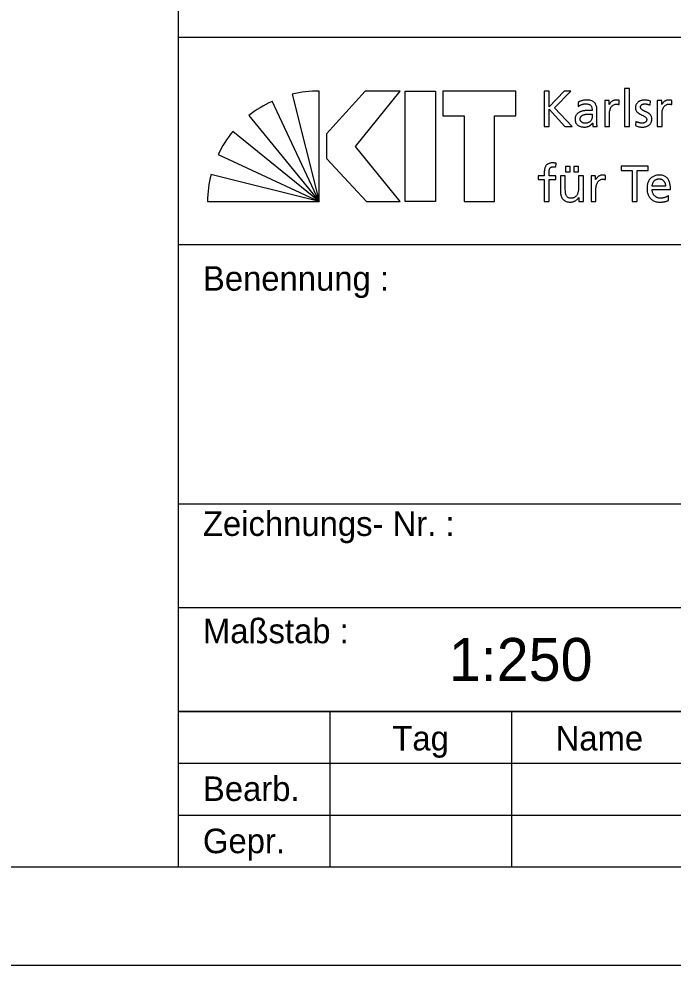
# Model space of a CAD drawing. Extents: x 0 to 105, y 0 to 74.
# Drawn here: x 78.75 to 92.08, y 0 to 19.29 of the extents above; entities that cross this region are included whole.
import ezdxf

# ---------------------------------------------------------------- set-up
doc = ezdxf.new("R2010")
doc.units = 0
doc.layers.add('90_Plankopf', color=7, linetype='Continuous')

msp = doc.modelspace()

# ---------------------------------------------------------------- linework, layer by layer
at = {"layer": '90_Plankopf'}
for p, q in [((82, 18.92), (82, 22.093)), ((82, 18.92), (103, 18.92)), ((84.319, 17.756), (84.87, 15.569)), ((84.87, 15.569), (84.87, 17.819)), ((89.452, 17.819), (89.452, 17.099)), ((84.87, 15.569), (83.908, 17.611)), ((90.145, 17.588), (90.15, 17.505)), ((90.982, 17.544), (90.982, 17.63)), ((91.614, 17.532), (91.622, 17.617)), ((92.053, 17.544), (92.053, 17.63)), ((90.53, 17.202), (90.53, 17.42)), ((83.436, 17.319), (84.87, 15.569)), ((90.433, 17.35), (90.433, 17.303)), ((91.324, 17.202), (91.319, 17.115)), ((84.87, 15.569), (83.108, 16.994)), ((89.452, 17.099), (89.556, 17.099)), ((89.876, 17.099), (90.027, 17.099)), ((82.81, 16.526), (84.87, 15.569)), ((89.693, 16.271), (89.697, 16.349)), ((84.87, 15.569), (82.664, 16.119)), ((90.707, 16.014), (90.707, 16.1)), ((91.927, 15.883), (91.654, 15.883)), ((91.654, 15.811), (92.03, 15.811)), ((91.989, 15.591), (91.989, 15.688)), ((82.591, 15.569), (84.87, 15.569)), ((82, 14.69), (103, 14.69)), ((82, 9.402), (103, 9.402)), ((82, 7.288), (103, 7.288)), ((82, 5.173), (103, 5.173)), ((82, 5.173), (103, 5.173)), ((82, 5.173), (103, 5.173)), ((82, 5.173), (103, 5.173)), ((82, 2), (82, 5.173)), ((85.088, 5.173), (85.088, 2)), ((88.794, 2), (88.794, 5.173)), ((82, 4.115), (92.5, 4.115)), ((82, 3.058), (92.5, 3.058)), ((82, 2), (103, 2)), ((82, 2), (103, 2))]:
    msp.add_line(p, q, dxfattribs=at)
for points in [[(0, 0), (105, 0), (105, 74.25), (0, 74.25)], [(2, 2), (103, 2), (103, 72.25), (2, 72.25)], [(86.517, 17.819), (85.809, 17.819), (85.018, 16.947), (85.018, 16.445), (85.834, 15.569), (86.521, 15.569), (85.606, 16.688)], [(87.243, 17.819), (87.243, 15.569), (86.625, 15.569), (86.625, 17.819)], [(87.391, 17.819), (87.391, 17.313), (87.825, 17.313), (87.825, 15.569), (88.443, 15.569), (88.443, 17.313), (88.877, 17.313), (88.877, 17.819)]]:
    msp.add_lwpolyline(points, close=True, dxfattribs=at)
for points in [[(82, 5.173), (82, 18.92)], [(90.027, 17.099), (89.662, 17.479), (90, 17.819), (89.863, 17.819), (89.556, 17.502), (89.556, 17.819), (89.452, 17.819)], [(91.095, 17.099), (91.192, 17.099), (91.192, 17.873), (91.095, 17.873), (91.095, 17.099)], [(90.78, 17.544), (90.778, 17.544), (90.778, 17.625), (90.688, 17.625), (90.688, 17.099), (90.785, 17.099), (90.785, 17.338)], [(91.852, 17.544), (91.85, 17.544), (91.85, 17.625), (91.759, 17.625), (91.759, 17.099), (91.856, 17.099), (91.856, 17.338)], [(89.556, 17.099), (89.556, 17.452), (89.876, 17.099)], [(90.441, 17.167), (90.443, 17.167), (90.443, 17.099), (90.534, 17.099)], [(89.889, 16.279), (89.889, 16.176), (89.986, 16.176), (89.986, 16.279), (89.889, 16.279)], [(90.058, 16.279), (90.058, 16.176), (90.155, 16.176), (90.155, 16.279), (90.058, 16.279)], [(91.248, 15.569), (91.351, 15.569), (91.351, 16.198), (91.575, 16.198), (91.575, 16.289), (91.024, 16.289), (91.024, 16.198), (91.248, 16.198), (91.248, 15.569)], [(89.456, 16.144), (89.456, 16.095), (89.332, 16.095), (89.332, 16.017), (89.456, 16.017), (89.456, 15.569), (89.553, 15.569), (89.553, 16.017), (89.692, 16.017), (89.692, 16.095), (89.553, 16.095), (89.553, 16.152)], [(89.885, 15.823), (89.885, 16.095), (89.788, 16.095), (89.788, 15.783)], [(90.254, 15.569), (90.254, 16.095), (90.157, 16.095), (90.157, 15.852)], [(90.506, 16.014), (90.504, 16.014), (90.504, 16.095), (90.413, 16.095), (90.413, 15.569), (90.51, 15.569), (90.51, 15.808)], [(90.158, 15.653), (90.16, 15.653), (90.16, 15.569), (90.254, 15.569)], [(103, 5.173), (82, 5.173)], [(82, 5.173), (82, 5.173)], [(82, 2), (103, 2)]]:
    msp.add_lwpolyline(points, dxfattribs=at)
for centre, start, end in [((84.862, 15.437), 89.8053, 103.1895), ((84.915, 15.452), 115.0126, 128.3968), ((84.954, 15.488), 140.7898, 154.174), ((84.973, 15.532), 165.7222, 179.1064)]:
    msp.add_arc(centre, 2.382, start, end, dxfattribs=at)
for points in [[(90.53, 17.42), (90.53, 17.468), (90.523, 17.508), (90.508, 17.54), (90.494, 17.572), (90.471, 17.597), (90.44, 17.613), (90.409, 17.629), (90.368, 17.637), (90.318, 17.637), (90.285, 17.637), (90.253, 17.633), (90.224, 17.624), (90.195, 17.615), (90.169, 17.603), (90.145, 17.588)], [(90.15, 17.505), (90.163, 17.516), (90.178, 17.526), (90.195, 17.534), (90.211, 17.542), (90.229, 17.548), (90.247, 17.553), (90.266, 17.557), (90.284, 17.559), (90.303, 17.559), (90.335, 17.559), (90.36, 17.554), (90.379, 17.544), (90.399, 17.533), (90.412, 17.518), (90.42, 17.498), (90.429, 17.477), (90.433, 17.452), (90.433, 17.422)], [(90.982, 17.63), (90.975, 17.632), (90.968, 17.633), (90.962, 17.634), (90.956, 17.635), (90.949, 17.636), (90.942, 17.636), (90.935, 17.637), (90.927, 17.637), (90.918, 17.637), (90.899, 17.637), (90.881, 17.633), (90.863, 17.625), (90.845, 17.617), (90.829, 17.606), (90.815, 17.592), (90.801, 17.578), (90.789, 17.562), (90.78, 17.544)], [(91.622, 17.617), (91.604, 17.623), (91.584, 17.628), (91.565, 17.631), (91.545, 17.635), (91.524, 17.637), (91.502, 17.637), (91.476, 17.637), (91.451, 17.634), (91.429, 17.628), (91.406, 17.621), (91.387, 17.611), (91.37, 17.598), (91.353, 17.584), (91.34, 17.567), (91.33, 17.547), (91.321, 17.527), (91.316, 17.503), (91.316, 17.476), (91.316, 17.455), (91.321, 17.436), (91.329, 17.421), (91.337, 17.406), (91.348, 17.392), (91.361, 17.381), (91.375, 17.37), (91.39, 17.36), (91.406, 17.351), (91.422, 17.343), (91.438, 17.334), (91.454, 17.327), (91.471, 17.319), (91.485, 17.311), (91.499, 17.303), (91.512, 17.295), (91.523, 17.286), (91.532, 17.276), (91.54, 17.266), (91.544, 17.254), (91.544, 17.24), (91.544, 17.226), (91.541, 17.214), (91.535, 17.205), (91.529, 17.195), (91.521, 17.187), (91.511, 17.181), (91.501, 17.175), (91.491, 17.171), (91.479, 17.169), (91.468, 17.166), (91.456, 17.165), (91.445, 17.165), (91.435, 17.165), (91.424, 17.166), (91.41, 17.169), (91.396, 17.172), (91.381, 17.176), (91.366, 17.182), (91.351, 17.187), (91.337, 17.194), (91.324, 17.202)], [(91.319, 17.115), (91.342, 17.104), (91.365, 17.096), (91.389, 17.092), (91.414, 17.088), (91.439, 17.086), (91.464, 17.087), (91.487, 17.087), (91.51, 17.09), (91.532, 17.096), (91.554, 17.103), (91.573, 17.113), (91.591, 17.126), (91.608, 17.14), (91.622, 17.157), (91.632, 17.178), (91.642, 17.198), (91.647, 17.223), (91.647, 17.251), (91.647, 17.275), (91.643, 17.295), (91.635, 17.311), (91.626, 17.328), (91.616, 17.342), (91.602, 17.354), (91.589, 17.366), (91.574, 17.375), (91.557, 17.384), (91.541, 17.392), (91.525, 17.4), (91.509, 17.407), (91.493, 17.414), (91.478, 17.421), (91.464, 17.429), (91.451, 17.437), (91.44, 17.446), (91.432, 17.457), (91.424, 17.467), (91.419, 17.48), (91.419, 17.495), (91.419, 17.51), (91.424, 17.522), (91.432, 17.531), (91.441, 17.541), (91.452, 17.548), (91.466, 17.552), (91.48, 17.557), (91.495, 17.559), (91.512, 17.559), (91.518, 17.559), (91.526, 17.558), (91.535, 17.557), (91.544, 17.555), (91.553, 17.553), (91.564, 17.551), (91.574, 17.548), (91.583, 17.545), (91.592, 17.542), (91.601, 17.539), (91.609, 17.536), (91.614, 17.532)], [(92.053, 17.63), (92.046, 17.632), (92.04, 17.633), (92.034, 17.634), (92.027, 17.635), (92.021, 17.636), (92.014, 17.636), (92.007, 17.637), (91.998, 17.637), (91.989, 17.637), (91.97, 17.637), (91.952, 17.633), (91.934, 17.625), (91.917, 17.617), (91.901, 17.606), (91.886, 17.592), (91.872, 17.578), (91.86, 17.562), (91.852, 17.544)], [(90.433, 17.422), (90.42, 17.423), (90.408, 17.423), (90.397, 17.423), (90.386, 17.424), (90.376, 17.424), (90.365, 17.424), (90.354, 17.424), (90.342, 17.424), (90.329, 17.424), (90.309, 17.424), (90.288, 17.422), (90.266, 17.419), (90.243, 17.415), (90.221, 17.409), (90.2, 17.401), (90.179, 17.393), (90.16, 17.382), (90.142, 17.369), (90.125, 17.355), (90.111, 17.339), (90.101, 17.319), (90.09, 17.3), (90.085, 17.277), (90.085, 17.251), (90.085, 17.213), (90.094, 17.181), (90.11, 17.157), (90.126, 17.133), (90.149, 17.115), (90.177, 17.104), (90.206, 17.092), (90.24, 17.087), (90.278, 17.087), (90.3, 17.087), (90.32, 17.089), (90.338, 17.095), (90.355, 17.1), (90.371, 17.107), (90.384, 17.115), (90.398, 17.123), (90.409, 17.132), (90.418, 17.141), (90.428, 17.15), (90.435, 17.159), (90.441, 17.167)], [(90.785, 17.338), (90.785, 17.383), (90.791, 17.421), (90.802, 17.453), (90.814, 17.485), (90.831, 17.509), (90.852, 17.527), (90.874, 17.544), (90.899, 17.553), (90.928, 17.553), (90.936, 17.553), (90.945, 17.552), (90.954, 17.551), (90.964, 17.55), (90.973, 17.547), (90.982, 17.544)], [(91.856, 17.338), (91.856, 17.383), (91.862, 17.421), (91.874, 17.453), (91.886, 17.485), (91.902, 17.509), (91.923, 17.527), (91.945, 17.544), (91.97, 17.553), (91.999, 17.553), (92.008, 17.553), (92.016, 17.552), (92.026, 17.551), (92.035, 17.55), (92.044, 17.547), (92.053, 17.544)], [(90.433, 17.303), (90.433, 17.277), (90.427, 17.253), (90.416, 17.233), (90.405, 17.212), (90.388, 17.195), (90.367, 17.183), (90.345, 17.171), (90.318, 17.165), (90.286, 17.165), (90.275, 17.165), (90.264, 17.167), (90.252, 17.17), (90.241, 17.174), (90.23, 17.18), (90.22, 17.187), (90.211, 17.194), (90.203, 17.203), (90.197, 17.214), (90.191, 17.224), (90.188, 17.237), (90.188, 17.251), (90.188, 17.269), (90.193, 17.285), (90.202, 17.297), (90.211, 17.309), (90.223, 17.319), (90.237, 17.326), (90.252, 17.334), (90.267, 17.339), (90.284, 17.343), (90.3, 17.347), (90.316, 17.349), (90.332, 17.35), (90.347, 17.351), (90.36, 17.352), (90.371, 17.352), (90.381, 17.352), (90.391, 17.351), (90.402, 17.351), (90.412, 17.35), (90.422, 17.35), (90.433, 17.35)], [(90.534, 17.099), (90.533, 17.104), (90.532, 17.111), (90.532, 17.119), (90.531, 17.128), (90.531, 17.139), (90.53, 17.152), (90.53, 17.166), (90.53, 17.182), (90.53, 17.202)], [(89.697, 16.349), (89.688, 16.351), (89.678, 16.352), (89.667, 16.353), (89.656, 16.355), (89.645, 16.355), (89.632, 16.355), (89.597, 16.355), (89.568, 16.35), (89.544, 16.34), (89.521, 16.33), (89.503, 16.316), (89.491, 16.297), (89.478, 16.279), (89.469, 16.257), (89.464, 16.231), (89.458, 16.205), (89.456, 16.176), (89.456, 16.144)], [(89.553, 16.152), (89.553, 16.17), (89.554, 16.186), (89.556, 16.202), (89.558, 16.217), (89.562, 16.23), (89.569, 16.241), (89.575, 16.252), (89.585, 16.261), (89.597, 16.267), (89.61, 16.274), (89.626, 16.277), (89.647, 16.277), (89.655, 16.277), (89.664, 16.276), (89.672, 16.275), (89.68, 16.274), (89.688, 16.273), (89.693, 16.271)], [(90.707, 16.1), (90.7, 16.102), (90.693, 16.103), (90.688, 16.104), (90.681, 16.105), (90.675, 16.106), (90.667, 16.107), (90.661, 16.107), (90.652, 16.108), (90.643, 16.108), (90.624, 16.107), (90.606, 16.103), (90.588, 16.095), (90.571, 16.088), (90.555, 16.077), (90.54, 16.062), (90.526, 16.048), (90.514, 16.032), (90.506, 16.014)], [(90.51, 15.808), (90.51, 15.853), (90.516, 15.891), (90.528, 15.923), (90.539, 15.955), (90.556, 15.98), (90.577, 15.997), (90.599, 16.014), (90.624, 16.023), (90.653, 16.023), (90.662, 16.023), (90.67, 16.023), (90.68, 16.021), (90.689, 16.02), (90.698, 16.017), (90.707, 16.014)], [(92.03, 15.811), (92.03, 15.853), (92.026, 15.892), (92.018, 15.928), (92.01, 15.964), (91.997, 15.996), (91.979, 16.023), (91.961, 16.049), (91.938, 16.07), (91.908, 16.085), (91.878, 16.1), (91.841, 16.107), (91.797, 16.108), (91.76, 16.107), (91.726, 16.101), (91.696, 16.088), (91.666, 16.075), (91.64, 16.057), (91.618, 16.033), (91.597, 16.009), (91.58, 15.981), (91.569, 15.949), (91.557, 15.916), (91.551, 15.881), (91.551, 15.841), (91.551, 15.798), (91.556, 15.76), (91.567, 15.725), (91.578, 15.69), (91.595, 15.66), (91.617, 15.635), (91.639, 15.61), (91.668, 15.591), (91.702, 15.577), (91.736, 15.564), (91.777, 15.557), (91.823, 15.557), (91.852, 15.557), (91.876, 15.559), (91.897, 15.563), (91.917, 15.566), (91.934, 15.571), (91.949, 15.576), (91.964, 15.581), (91.977, 15.586), (91.989, 15.591)], [(91.654, 15.883), (91.656, 15.9), (91.66, 15.917), (91.666, 15.934), (91.672, 15.951), (91.681, 15.967), (91.692, 15.982), (91.703, 15.996), (91.717, 16.007), (91.734, 16.016), (91.751, 16.025), (91.772, 16.029), (91.795, 16.029), (91.816, 16.029), (91.835, 16.025), (91.851, 16.018), (91.867, 16.01), (91.881, 16), (91.892, 15.986), (91.903, 15.973), (91.912, 15.957), (91.918, 15.94), (91.924, 15.922), (91.927, 15.903), (91.927, 15.883)], [(90.157, 15.852), (90.157, 15.82), (90.154, 15.79), (90.147, 15.764), (90.141, 15.737), (90.131, 15.715), (90.118, 15.695), (90.105, 15.676), (90.088, 15.661), (90.068, 15.651), (90.048, 15.64), (90.024, 15.635), (89.997, 15.635), (89.969, 15.637), (89.947, 15.645), (89.93, 15.659), (89.914, 15.673), (89.902, 15.694), (89.895, 15.721), (89.889, 15.748), (89.885, 15.782), (89.885, 15.823)], [(89.788, 15.783), (89.788, 15.735), (89.795, 15.695), (89.809, 15.661), (89.823, 15.628), (89.845, 15.602), (89.874, 15.584), (89.903, 15.566), (89.94, 15.557), (89.986, 15.557), (90.01, 15.557), (90.034, 15.561), (90.056, 15.568), (90.079, 15.576), (90.099, 15.587), (90.117, 15.601), (90.134, 15.616), (90.148, 15.633), (90.158, 15.653)], [(91.989, 15.688), (91.983, 15.683), (91.975, 15.677), (91.963, 15.671), (91.952, 15.665), (91.939, 15.66), (91.924, 15.654), (91.909, 15.649), (91.893, 15.644), (91.876, 15.641), (91.86, 15.637), (91.844, 15.635), (91.827, 15.635), (91.804, 15.635), (91.782, 15.639), (91.762, 15.648), (91.741, 15.656), (91.722, 15.668), (91.706, 15.684), (91.69, 15.699), (91.677, 15.718), (91.668, 15.739), (91.659, 15.761), (91.654, 15.784), (91.654, 15.811)]]:
    msp.add_open_spline(points, degree=3, dxfattribs=at)

# ---------------------------------------------------------------- texts
for s, height, p in [('Benennung :', 0.5, (82.5, 13.75)), ('Zeichnungs- Nr. :', 0.5, (82.5, 8.75)), ('Maßstab :', 0.5, (82.5, 6.562)), ('1:250   ', 0.875, (87.512, 5.794)), ('Tag', 0.5, (86.36, 4.375)), ('Name', 0.5, (89.688, 4.375)), ('Bearb.', 0.5, (82.5, 3.346)), ('Gepr.', 0.5, (82.5, 2.281))]:
    msp.add_text(s, height=height, dxfattribs=at).set_placement(p)

doc.saveas('drawing.dxf')
